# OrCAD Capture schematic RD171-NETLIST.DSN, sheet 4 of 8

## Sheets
4 5: size A3
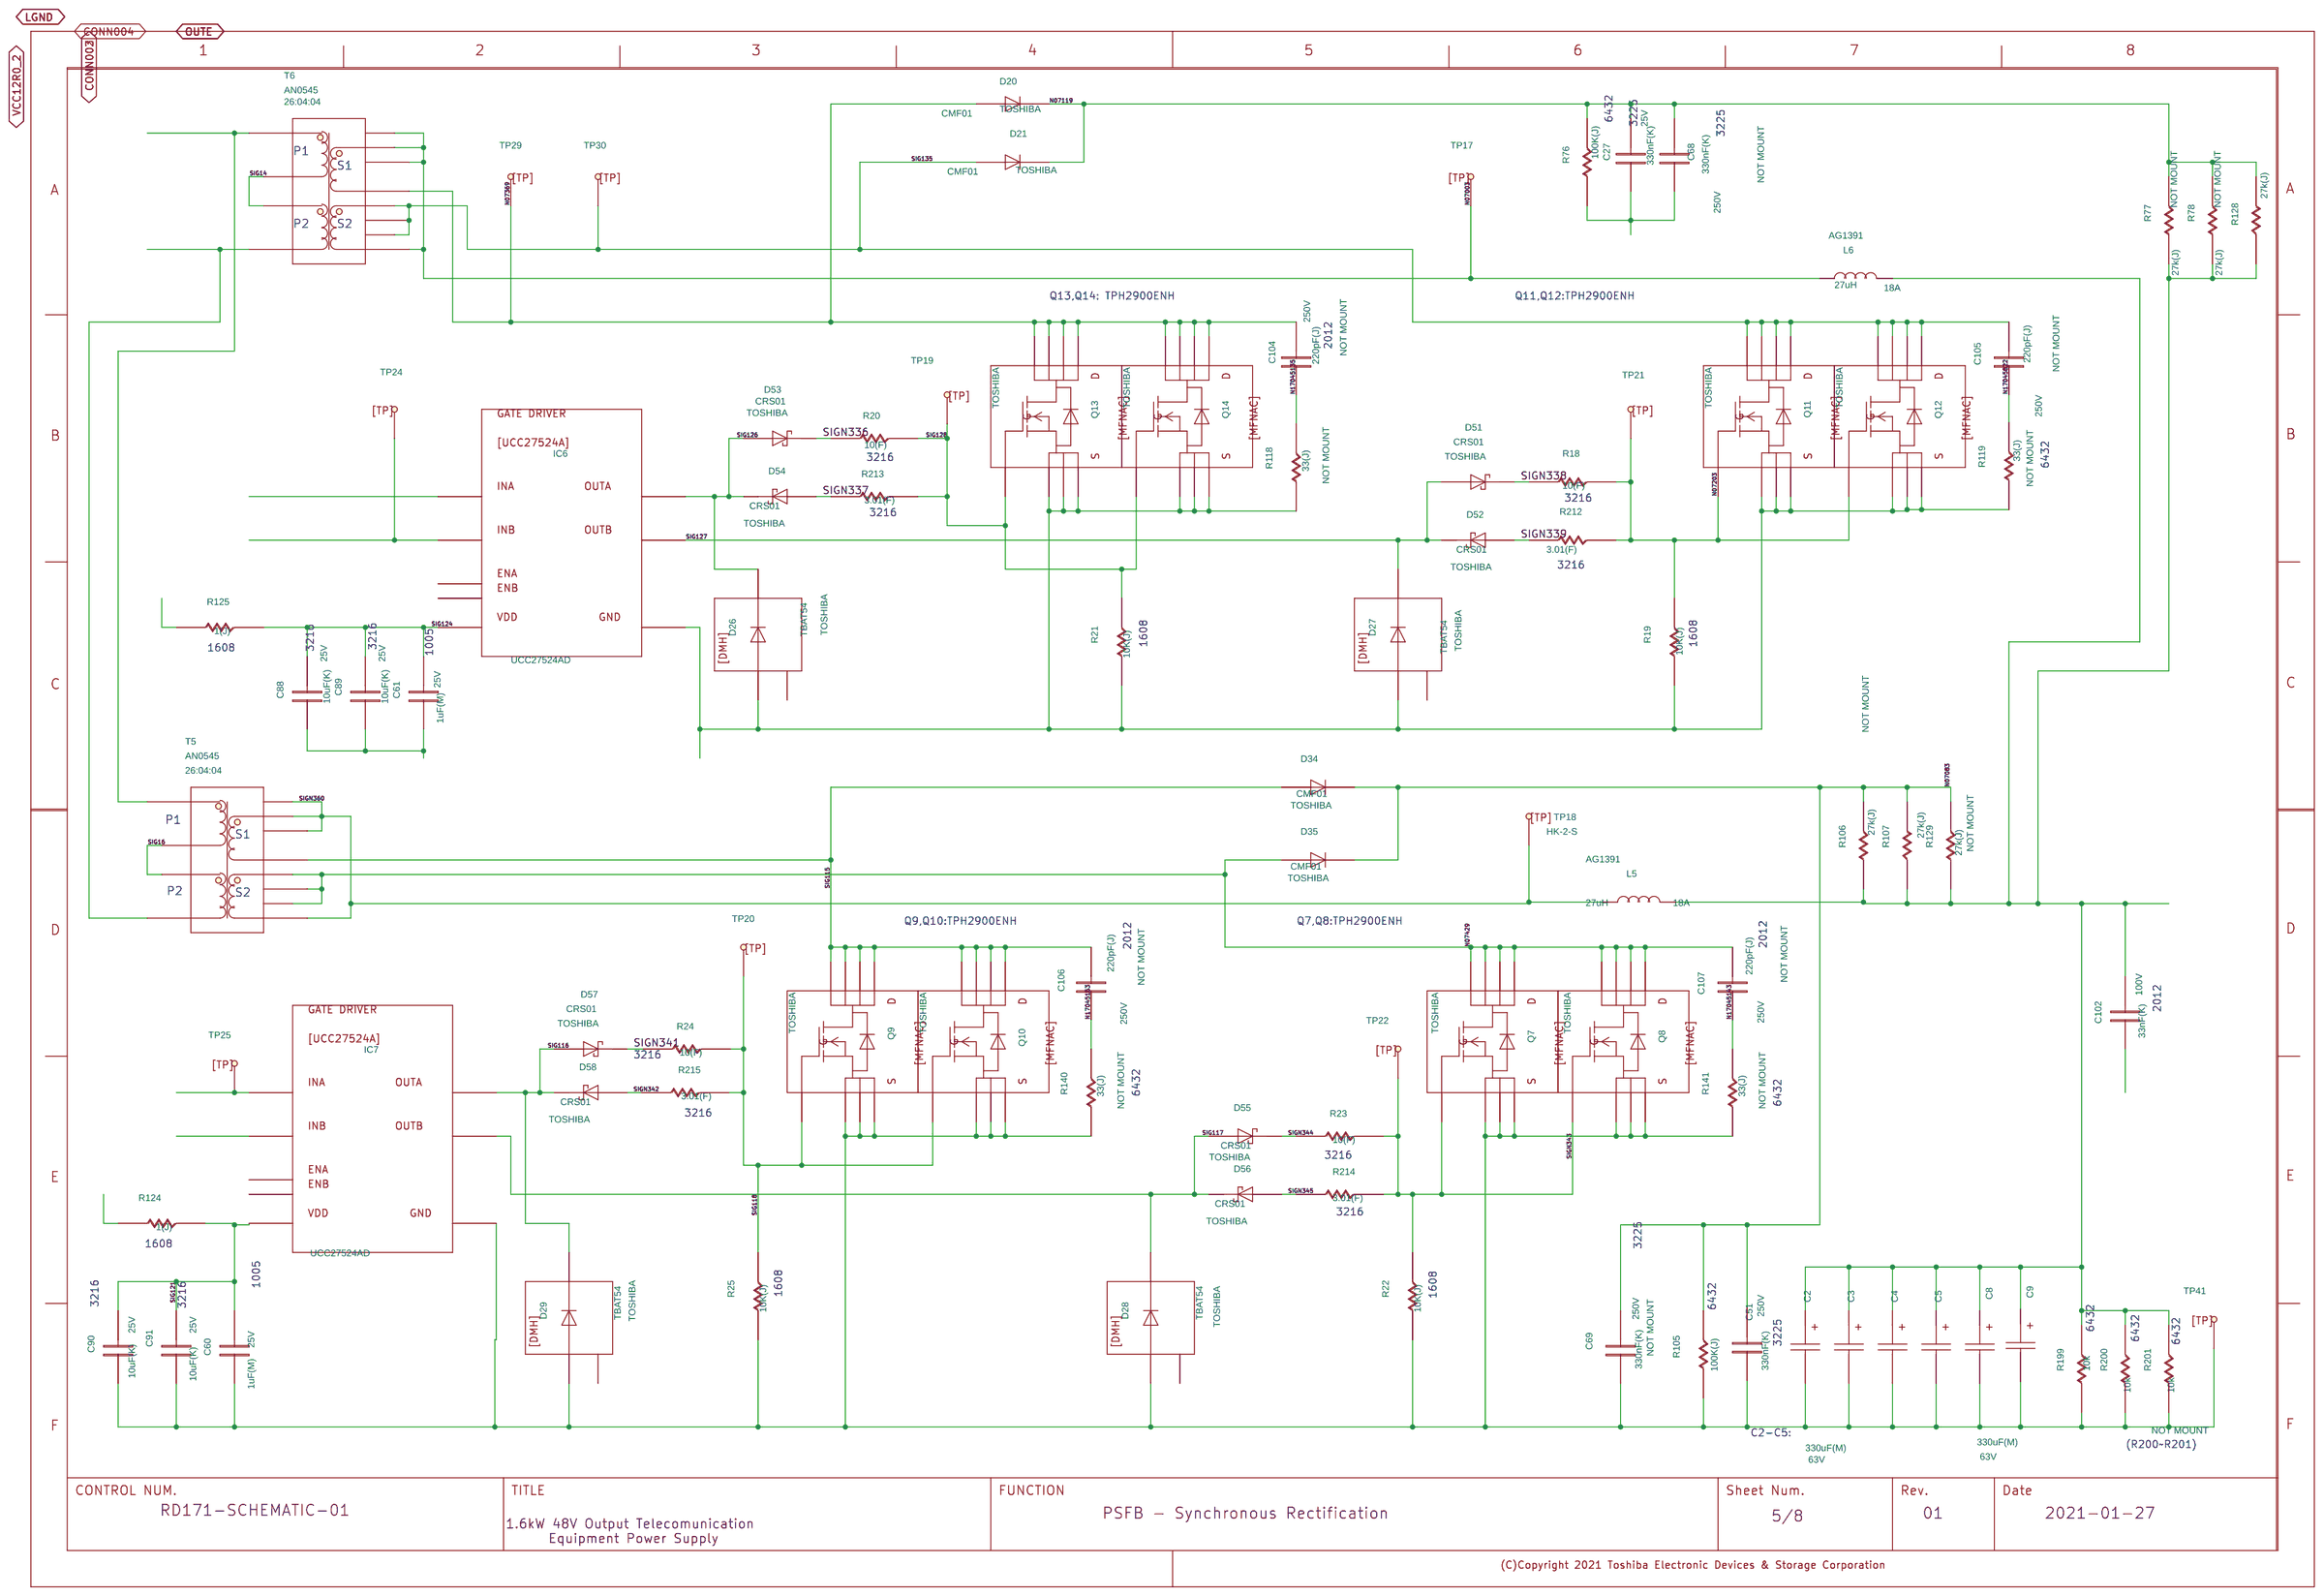
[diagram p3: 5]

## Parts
C2  330uF  [EKZN630ELL331MJ25S]
C3  330uF  [EKZN630ELL331MJ25S]
C4  330uF  [EKZN630ELL331MJ25S]
C5  330uF  [EKZN630ELL331MJ25S]
C8  330uF  [EKZN630ELL331MJ25S]
C9  330uF  [EKZN630ELL331MJ25S]
C27  330nF  [C3225X7T2E334K200AE]
C51  330nF  [C3225X7T2E334K200AE]
C60  1uF
C61  1uF
C68  330nF  [C3225X7T2E334K200AE]
C69  330nF  [C3225X7T2E334K200AE]
C88  10uF
C89  10uF
C90  10uF
C91  10uF
C102  33nF  [C2012C0G2A333J125AE]
C104  220pF  [GRM21A5C221J]
C105  220pF  [GRM21A5C221J]
C106  220pF  [GRM21A5C221J]
C107  220pF  [GRM21A5C221J]
D20  D20  [CMF01]
D21  D21  [CMF01]
D26  D26  [TBAT54]
D27  D27  [TBAT54]
D28  D28  [TBAT54]
D29  D29  [TBAT54]
D34  D34  [CMF01]
D35  D35  [CMF01]
D51  D51  [CRS01]
D52  D52  [CRS01]
D53  D53  [CRS01]
D54  D54  [CRS01]
D55  D55  [CRS01]
D56  D56  [CRS01]
D57  D57  [CRS01]
D58  D58  [CRS01]
IC6  IC6  [UCC27524AD]
IC7  IC7  [UCC27524AD]
L5  27uH  [AG-1391]
L6  27uH  [AG-1391]
Q7  Q7  [TPH2900ENH]
Q8  Q8  [TPH2900ENH]
Q9  Q9  [TPH2900ENH]
Q10  Q10  [TPH2900ENH]
Q11  Q11  [TPH2900ENH]
Q12  Q12  [TPH2900ENH]
Q13  Q13  [TPH2900ENH]
Q14  Q14  [TPH2900ENH]
R18  10
R19  10k
R20  10
R21  10k
R22  10k
R23  10
R24  10
R25  10k
R76  100k  [RK73B3ATTE104J]
R77  R  [MOS3CT631R273J]
R78  27k  [MOS3CT631R273J]
R105  100k  [RK73B3ATTE104J]
R106  27k  [MOS3CT631R273J]
R107  27k  [MOS3CT631R273J]
R118  33  [RK73B3ATTE330J]
R119  33  [RK73B3ATTE330J]
R124  1
R125  1
R128  27k  [MOS3CT631R273J]
R129  27k  [MOS3CT631R273J]
R140  33  [RK73B3ATTE330J]
R141  33  [RK73B3ATTE330J]
R199  10k  [RK73B3ATTE104J]
R200  10k  [RK73B3ATTE104J]
R201  10k  [RK73B3ATTE104J]
R212  3.01
R213  3.01
R214  3.01
R215  3.01
T5  T3_12V67A
T6  T3_12V67A
TP17  TP17  [HK-2-S]
TP18  TP18  [HK-2-S]
TP19  TP19  [HK-2-S]
TP20  TP20  [HK-2-S]
TP21  TP21  [HK-2-S]
TP22  TP22  [HK-2-S]
TP24  TP24  [HK-2-S]
TP25  TP25  [HK-2-S]
TP29  TP29  [HK-2-S]
TP30  TP30  [HK-2-S]
TP41  TP41  [LC-22-S-BLACK]
U?#3  WAKU_DEF100

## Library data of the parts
C2 = CP: CAPACITANCETOLE: M; CDMASTERCADCELG: DC0341; CHIPSIZE: D10xL22; COMP: PRT_3; COMPONENTNAME: CP_CP.Normal_package; FNLEADFREETHET1GT2GMCTH1: 0_2_N; FUNCTION: CP_CP.Normal_package; GCOUNT: 1; INSTANCENAME: INS5781; MAKER: RUBYCON; MAXGCOUNT: 1; NOMINALCAPACITA: 56u; OUMECLASSIFICATION: ƒAƒ‹ƒ~“d‰ðƒRƒ“ƒfƒ“ƒT; OUMEPARTTYPE: C; PARTNAME: EKZN630ELL331MJ25S_CC; PMPRODUCTSTYPEG: SV1; QUADMODEL: CON_56U; RATEDVOLTAGE: 16; SIZECODESMD: DIP; VAL1: 330uF(M); VAL2: 63V
C3 = CP: CAPACITANCETOLE: M; CHIPSIZE: D10xL22; COMP: PRT_3; COMPONENTNAME: CP_CP.Normal_package; FUNCTION: CP_CP.Normal_package; GCOUNT: 1; INSTANCENAME: INS5793; MAKER: RUBYCON; MAXGCOUNT: 1; NOMINALCAPACITA: 56u; PARTNAME: EKZN630ELL331MJ25S_CC; PMPRODUCTSTYPEG: SV1; RATEDVOLTAGE: 16; SIZECODESMD: DIP; VAL1: 330uF(M); VAL2: 63V; VAL3: 25ZLQ1500MEFC10X25
C4 = CP: CAPACITANCETOLE: M; CHIPSIZE: D10xL22; COMP: PRT_3; COMPONENTNAME: CP_CP.Normal_package; FUNCTION: CP_CP.Normal_package; GCOUNT: 1; INSTANCENAME: INS5801; MAKER: RUBYCON; MAXGCOUNT: 1; NOMINALCAPACITA: 56u; PARTNAME: EKZN630ELL331MJ25S_CC; PMPRODUCTSTYPEG: SV1; RATEDVOLTAGE: 16; SIZECODESMD: DIP; VAL1: 330uF(M); VAL2: 63V; VAL3: 25ZLQ1500MEFC10X25
C5 = CP: CAPACITANCETOLE: M; CHIPSIZE: D10xL22; COMP: PRT_3; COMPONENTNAME: CP_CP.Normal_package; FUNCTION: CP_CP.Normal_package; GCOUNT: 1; INSTANCENAME: INS5809; MAKER: RUBYCON; MAXGCOUNT: 1; NOMINALCAPACITA: 56u; PARTNAME: EKZN630ELL331MJ25S_CC; PMPRODUCTSTYPEG: SV1; RATEDVOLTAGE: 16; SIZECODESMD: DIP; VAL1: 330uF(M); VAL2: 63V; VAL3: 25ZLQ1500MEFC10X25
C8 = CP: CAPACITANCETOLE: M; CHIPSIZE: D10xL22; COMP: PRT_3; COMPONENTNAME: CP_CP.Normal_package; FUNCTION: CP_CP.Normal_package; GCOUNT: 1; INSTANCENAME: INS17034209; MAKER: RUBYCON; MAXGCOUNT: 1; NOMINALCAPACITA: 56u; PARTNAME: EKZN630ELL331MJ25S_CC; PMPRODUCTSTYPEG: SV1; RATEDVOLTAGE: 16; SIZECODESMD: DIP; VAL1: 330uF(M); VAL2: 63V; VAL3: EKZN630ELL331M
C9 = CP: CAPACITANCETOLE: M; CHIPSIZE: D10xL22; COMP: PRT_3; COMPONENTNAME: CP_CP.Normal_package; FUNCTION: CP_CP.Normal_package; GCOUNT: 1; INSTANCENAME: INS17035630; MAKER: RUBYCON; MAXGCOUNT: 1; NOMINALCAPACITA: 56u; PARTNAME: EKZN630ELL331MJ25S_CC; PMPRODUCTSTYPEG: SV1; RATEDVOLTAGE: 16; SIZECODESMD: DIP; VAL1: 330uF(M); VAL2: 63V; VAL3: EKZN630ELL331M
C27 = C: ADSMODELNAME: s_C1005JB1C224KT; CAPACITANCETOLE: K; CDMASTERCADCELG: KC0005; CHIPSIZE: 1005; COMP: PRT_52; COMPONENTNAME: C_C.Normal_package; FNLEADFREETHET1GT2GMCTH1: N_N_N; FUNCTION: C_C.Normal_package; GCOUNT: 1; INSTANCENAME: INS6475; MAKER: TDK; MAXGCOUNT: 1; NOMINALCAPACITA: 220n; OUMECLASSIFICATION: ƒZƒ‰ƒ~ƒbƒNƒRƒ“ƒfƒ“ƒT; OUMEMAKER: TDK ‚s‚c‚j; OUMEMAKERKATAMEI: C1005JB1C224KT; PARTNAME: Chip3225_GS_1; QUADMODEL: CON_220N; RATEDVOLTAGE: 16; SIZECODESMD: 1005; TEMPCHARACTERI2: B; VAL1: 330nF(K); VAL2: 25V; VAL3: C1005X5R1E224K050BC
C51 = C: ADSMODELNAME: s_C1005JB1C224KT; CAPACITANCETOLE: K; CDMASTERCADCELG: KC0005; CHIPSIZE: 1005; COMP: PRT_52; COMPONENTNAME: C_C.Normal_package; FNLEADFREETHET1GT2GMCTH1: N_N_N; FUNCTION: C_C.Normal_package; GCOUNT: 1; INSTANCENAME: INS17062697; MAKER: TDK; MAXGCOUNT: 1; NOMINALCAPACITA: 220n; OUMECLASSIFICATION: ƒZƒ‰ƒ~ƒbƒNƒRƒ“ƒfƒ“ƒT; OUMEMAKER: TDK ‚s‚c‚j; PARTNAME: Chip3225_GS_1; QUADMODEL: CON_220N; RATEDVOLTAGE: 16; SIZECODESMD: 3225; TEMPCHARACTERI2: B; VAL1: 330nF(K); VAL2: 250V
C60 = C: ADSMODELNAME: s_GRM155B31E105KA12D; CAPACITANCETOLE: K; CDMASTERCADCELG: KC0005; CHIPSIZE: 1005; COMP: PRT_52; COMPONENTNAME: C_C.Normal_package; FNLEADFREETHET1GT2GMCTH1: 3_0_N; FUNCTION: C_C.Normal_package; GCOUNT: 1; INSTANCENAME: INS6615; MAKER: TDK; MAXGCOUNT: 1; NOMINALCAPACITA: 1u; OUMECLASSIFICATION: ƒZƒ‰ƒ~ƒbƒNƒRƒ“ƒfƒ“ƒT; OUMEMAKER: MRT ºc»ì; OUMEMAKERKATAMEI: GRM155B31E105KA12D; PARTNAME: Chip1005_GS_2; PMPRODUCTSTYPEG: HD1; QUADMODEL: CON_1U; RATEDVOLTAGE: 25; SIZECODESMD: 1005; TEMPCHARACTERI2: B; VAL1: 1uF(M); VAL2: 25V; VAL3: C1005X5R1E105M050BC
C61 = C: ADSMODELNAME: s_GRM155B31E105KA12D; CAPACITANCETOLE: K; CDMASTERCADCELG: KC0005; CHIPSIZE: 1005; COMP: PRT_52; COMPONENTNAME: C_C.Normal_package; FNLEADFREETHET1GT2GMCTH1: 3_0_N; FUNCTION: C_C.Normal_package; GCOUNT: 1; INSTANCENAME: INS6565; MAKER: TDK; MAXGCOUNT: 1; NOMINALCAPACITA: 1u; OUMECLASSIFICATION: ƒZƒ‰ƒ~ƒbƒNƒRƒ“ƒfƒ“ƒT; OUMEMAKER: MRT ºc»ì; OUMEMAKERKATAMEI: GRM155B31E105KA12D; PARTNAME: Chip1005_GS_2; PMPRODUCTSTYPEG: HD1; QUADMODEL: CON_1U; RATEDVOLTAGE: 25; SIZECODESMD: 1005; TEMPCHARACTERI2: B; VAL1: 1uF(M); VAL2: 25V; VAL3: C1005X5R1E105M050BC
C68 = C: ADSMODELNAME: s_C1005JB1C224KT; CAPACITANCETOLE: K; CDMASTERCADCELG: KC0005; CHIPSIZE: 1005; COMP: PRT_52; COMPONENTNAME: C_C.Normal_package; FNLEADFREETHET1GT2GMCTH1: N_N_N; FUNCTION: C_C.Normal_package; GCOUNT: 1; INSTANCENAME: INS17036811; MAKER: TDK; MAXGCOUNT: 1; MOUNT: NOT MOUNT; NOMINALCAPACITA: 220n; NOTMOUNT: NOT MOUNT; OUMECLASSIFICATION: ƒZƒ‰ƒ~ƒbƒNƒRƒ“ƒfƒ“ƒT; OUMEMAKER: TDK ‚s‚c‚j; PARTNAME: Chip3225_GS_1; QUADMODEL: CON_220N; RATEDVOLTAGE: 16; SIZECODESMD: 3225; TEMPCHARACTERI2: B; VAL1: 330nF(K); VAL2: 250V
C69 = C: ADSMODELNAME: s_C1005JB1C224KT; CAPACITANCETOLE: K; CDMASTERCADCELG: KC0005; CHIPSIZE: 1005; COMP: PRT_52; COMPONENTNAME: C_C.Normal_package; FNLEADFREETHET1GT2GMCTH1: N_N_N; FUNCTION: C_C.Normal_package; GCOUNT: 1; INSTANCENAME: INS17039422; MAKER: TDK; MAXGCOUNT: 1; MOUNT: NOT MOUNT; NOMINALCAPACITA: 220n; NOTMOUNT: NOT MOUNT; OUMECLASSIFICATION: ƒZƒ‰ƒ~ƒbƒNƒRƒ“ƒfƒ“ƒT; OUMEMAKER: TDK ‚s‚c‚j; PARTNAME: Chip3225_GS_1; QUADMODEL: CON_220N; RATEDVOLTAGE: 16; SIZECODESMD: 3225; TEMPCHARACTERI2: B; VAL1: 330nF(K); VAL2: 250V
C88 = C: ADSMODELNAME: s_TMK316LD106KL_T; CAPACITANCETOLE: K; CDMASTERCADCELG: KC0014; CHIPSIZE: 3216; COMP: PRT_46; COMPONENTNAME: C_C.Normal_package; FNLEADFREETHET1GT2GMCTH1: N_N_N; FUNCTION: C_C.Normal_package; GCOUNT: 1; INSTANCENAME: INS6555; MAKER: TAIYO YUDEN; MAXGCOUNT: 1; NOMINALCAPACITA: 10u; OUMECLASSIFICATION: ƒZƒ‰ƒ~ƒbƒNƒRƒ“ƒfƒ“ƒT; OUMEMAKER: TYD ‘¾—z—U“d; OUMEMAKERKATAMEI: TMK316LD106KL-T; PARTNAME: Chip3216_GS_1; QUADMODEL: CON_10U; RATEDVOLTAGE: 25; SIZECODESMD: 3216; VAL1: 10uF(K); VAL2: 25V; VAL3: TMK316BJ106KL-T
C89 = C: ADSMODELNAME: s_TMK316LD106KL_T; CAPACITANCETOLE: K; CDMASTERCADCELG: KC0014; CHIPSIZE: 3216; COMP: PRT_46; COMPONENTNAME: C_C.Normal_package; FNLEADFREETHET1GT2GMCTH1: N_N_N; FUNCTION: C_C.Normal_package; GCOUNT: 1; INSTANCENAME: INS6545; MAKER: TAIYO YUDEN; MAXGCOUNT: 1; NOMINALCAPACITA: 10u; OUMECLASSIFICATION: ƒZƒ‰ƒ~ƒbƒNƒRƒ“ƒfƒ“ƒT; OUMEMAKER: TYD ‘¾—z—U“d; OUMEMAKERKATAMEI: TMK316LD106KL-T; PARTNAME: Chip3216_GS_1; QUADMODEL: CON_10U; RATEDVOLTAGE: 25; SIZECODESMD: 3216; VAL1: 10uF(K); VAL2: 25V; VAL3: TMK316BJ106KL-T
C90 = C: ADSMODELNAME: s_TMK316LD106KL_T; CAPACITANCETOLE: K; CDMASTERCADCELG: KC0014; CHIPSIZE: 3216; COMP: PRT_46; COMPONENTNAME: C_C.Normal_package; FNLEADFREETHET1GT2GMCTH1: N_N_N; FUNCTION: C_C.Normal_package; GCOUNT: 1; INSTANCENAME: INS6595; MAKER: TAIYO YUDEN; MAXGCOUNT: 1; NOMINALCAPACITA: 10u; OUMECLASSIFICATION: ƒZƒ‰ƒ~ƒbƒNƒRƒ“ƒfƒ“ƒT; OUMEMAKER: TYD ‘¾—z—U“d; OUMEMAKERKATAMEI: TMK316LD106KL-T; PARTNAME: Chip3216_GS_1; QUADMODEL: CON_10U; RATEDVOLTAGE: 25; SIZECODESMD: 3216; VAL1: 10uF(K); VAL2: 25V; VAL3: TMK316BJ106KL-T
C91 = C: ADSMODELNAME: s_TMK316LD106KL_T; CAPACITANCETOLE: K; CDMASTERCADCELG: KC0014; CHIPSIZE: 3216; COMP: PRT_46; COMPONENTNAME: C_C.Normal_package; FNLEADFREETHET1GT2GMCTH1: N_N_N; FUNCTION: C_C.Normal_package; GCOUNT: 1; INSTANCENAME: INS6605; MAKER: TAIYO YUDEN; MAXGCOUNT: 1; NOMINALCAPACITA: 10u; OUMECLASSIFICATION: ƒZƒ‰ƒ~ƒbƒNƒRƒ“ƒfƒ“ƒT; OUMEMAKER: TYD ‘¾—z—U“d; OUMEMAKERKATAMEI: TMK316LD106KL-T; PARTNAME: Chip3216_GS_1; QUADMODEL: CON_10U; RATEDVOLTAGE: 25; SIZECODESMD: 3216; VAL1: 10uF(K); VAL2: 25V; VAL3: TMK316BJ106KL-T
C102 = C: ADSMODELNAME: s_GRM155R71E104KE14D; CAPACITANCETOLE: K; CDMASTERCADCELG: KC0005; CHIPSIZE: 1005; COMP: PRT_52; COMPONENTNAME: C_C.Normal_package; FNLEADFREETHET1GT2GMCTH1: N_N_N; FUNCTION: C_C.Normal_package; GCOUNT: 1; INSTANCENAME: INS6675; MAKER: TDK; MAXGCOUNT: 1; NOMINALCAPACITA: 100n; OUMECLASSIFICATION: ƒZƒ‰ƒ~ƒbƒNƒRƒ“ƒfƒ“ƒT; OUMEMAKER: MRT ºc»ì; OUMEMAKERKATAMEI: GRM155R71E104KE14D; PARTNAME: Chip2012_GS_1; QUADMODEL: CON_100N; RATEDVOLTAGE: 25; SIZECODESMD: 1005; VAL1: 33nF(K); VAL2: 100V
C104 = C: ADSMODELNAME: s_GRM155R71E104KE14D; CAPACITANCETOLE: K; CDMASTERCADCELG: KC0005; CHIPSIZE: 2012; COMP: PRT_52; COMPONENTNAME: C_C.Normal_package; FNLEADFREETHET1GT2GMCTH1: N_N_N; FUNCTION: C_C.Normal_package; GCOUNT: 1; INSTANCENAME: INS17040886; MAKER: MURATA; MAXGCOUNT: 1; MOUNT: NOT MOUNT; NOMINALCAPACITA: 100n; NOTMOUNT: NOT MOUNT; OUMECLASSIFICATION: ƒZƒ‰ƒ~ƒbƒNƒRƒ“ƒfƒ“ƒT; OUMEMAKER: MRT ºc»ì; OUMEMAKERKATAMEI: GRM21A5C2E221JW01D; PARTNAME: Chip2012_GS_1; QUADMODEL: CON_100N; RATEDVOLTAGE: 250; SIZECODESMD: 2012; VAL1: 220pF(J); VAL2: 250V; VAL3: GRM21A5C2E221J
C105 = C: ADSMODELNAME: s_GRM155R71E104KE14D; CAPACITANCETOLE: K; CDMASTERCADCELG: KC0005; CHIPSIZE: 2012; COMP: PRT_52; COMPONENTNAME: C_C.Normal_package; FNLEADFREETHET1GT2GMCTH1: N_N_N; FUNCTION: C_C.Normal_package; GCOUNT: 1; INSTANCENAME: INS17040900; MAKER: MURATA; MAXGCOUNT: 1; MOUNT: NOT MOUNT; NOMINALCAPACITA: 100n; NOTMOUNT: NOT MOUNT; OUMECLASSIFICATION: ƒZƒ‰ƒ~ƒbƒNƒRƒ“ƒfƒ“ƒT; OUMEMAKER: MRT ºc»ì; OUMEMAKERKATAMEI: GRM21A5C2E221JW01D; PARTNAME: Chip2012_GS_1; QUADMODEL: CON_100N; RATEDVOLTAGE: 250; SIZECODESMD: 2012; VAL1: 220pF(J); VAL2: 250V; VAL3: GRM21A5C2E221J
C106 = C: ADSMODELNAME: s_GRM155R71E104KE14D; CAPACITANCETOLE: K; CDMASTERCADCELG: KC0005; CHIPSIZE: 2012; COMP: PRT_52; COMPONENTNAME: C_C.Normal_package; FNLEADFREETHET1GT2GMCTH1: N_N_N; FUNCTION: C_C.Normal_package; GCOUNT: 1; INSTANCENAME: INS17040913; MAKER: MURATA; MAXGCOUNT: 1; MOUNT: NOT MOUNT; NOMINALCAPACITA: 100n; NOTMOUNT: NOT MOUNT; OUMECLASSIFICATION: ƒZƒ‰ƒ~ƒbƒNƒRƒ“ƒfƒ“ƒT; OUMEMAKER: MRT ºc»ì; OUMEMAKERKATAMEI: GRM21A5C2E221JW01D; PARTNAME: Chip2012_GS_1; QUADMODEL: CON_100N; RATEDVOLTAGE: 250; SIZECODESMD: 2012; VAL1: 220pF(J); VAL2: 250V; VAL3: GRM21A5C2E221J
C107 = C: ADSMODELNAME: s_GRM155R71E104KE14D; CAPACITANCETOLE: K; CDMASTERCADCELG: KC0005; CHIPSIZE: 2012; COMP: PRT_52; COMPONENTNAME: C_C.Normal_package; FNLEADFREETHET1GT2GMCTH1: N_N_N; FUNCTION: C_C.Normal_package; GCOUNT: 1; INSTANCENAME: INS17040926; MAKER: MURATA; MAXGCOUNT: 1; MOUNT: NOT MOUNT; NOMINALCAPACITA: 100n; NOTMOUNT: NOT MOUNT; OUMECLASSIFICATION: ƒZƒ‰ƒ~ƒbƒNƒRƒ“ƒfƒ“ƒT; OUMEMAKER: MRT ºc»ì; OUMEMAKERKATAMEI: GRM21A5C2E221JW01D; PARTNAME: Chip2012_GS_1; QUADMODEL: CON_100N; RATEDVOLTAGE: 250; SIZECODESMD: 2012; VAL1: 220pF(J); VAL2: 250V; VAL3: GRM21A5C2E221J
D20 = D: ADSMODELNAME: s_MURS340T3G@@; CDMASTERCADCELG: KD0125; COMP: PRT_14; COMPONENTNAME: D_D.Normal_package; FNLEADFREETHET1GT2GMCTH1: N_N_N; FORWARDVOLTAGEM: 0; FUNCTION: D_D.Normal_package; GCOUNT: 1; INSTANCENAME: INS5897; MAKER: TOSHIBA; MAXAVERAGEFORWA: 4; MAXGCOUNT: 1; MAXREPETITIVEPE: 400; MAXREVERSEVOLTA: 0; MOUNTINGFORMSMD: SMD; OUMECLASSIFICATION: êÊ®¬fq; OUMEMAKER: ONS IZ~R_N^[; OUMEMAKERKATAMEI: MURS340T3G@@; PARTNAME: CMF01_TS_B; PEAKFORWARDVOLT: 1.28; PMPRODUCTSTYPEG: HEV; REVERSECURRENT: 250u; USERCOMPTEXT3: TOSHIBA; ZENERVOLTAGEMAX: 0; ZENERVOLTAGEMIN: 0
D21 = D: ADSMODELNAME: s_MURS340T3G@@; CDMASTERCADCELG: KD0125; COMP: PRT_14; COMPONENTNAME: D_D.Normal_package; FNLEADFREETHET1GT2GMCTH1: N_N_N; FORWARDVOLTAGEM: 0; FUNCTION: D_D.Normal_package; GCOUNT: 1; INSTANCENAME: INS5909; MAKER: TOSHIBA; MAXAVERAGEFORWA: 4; MAXGCOUNT: 1; MAXREPETITIVEPE: 400; MAXREVERSEVOLTA: 0; MOUNTINGFORMSMD: SMD; OUMECLASSIFICATION: êÊ®¬fq; OUMEMAKER: ONS IZ~R_N^[; OUMEMAKERKATAMEI: MURS340T3G@@; PARTNAME: CMF01_TS_B; PEAKFORWARDVOLT: 1.28; PMPRODUCTSTYPEG: HEV; REVERSECURRENT: 250u; USERCOMPTEXT3: TOSHIBA; ZENERVOLTAGEMAX: 0; ZENERVOLTAGEMIN: 0
D26 = DMH: COMP: PRT_25; COMPONENTNAME: DMH_DMH.Normal_package; FUNCTION: DMH_DMH.Normal_package; INSTANCENAME: INS5825; MAKER: TOSHIBA; PARTNAME: TBAT54_TS_B; USERCOMPTEXT3: TOSHIBA
D27 = DMH: COMP: PRT_25; COMPONENTNAME: DMH_DMH.Normal_package; FUNCTION: DMH_DMH.Normal_package; INSTANCENAME: INS5883; MAKER: TOSHIBA; PARTNAME: TBAT54_TS_B; USERCOMPTEXT3: TOSHIBA
D28 = DMH: COMP: PRT_25; COMPONENTNAME: DMH_DMH.Normal_package; FUNCTION: DMH_DMH.Normal_package; INSTANCENAME: INS5767; MAKER: TOSHIBA; PARTNAME: TBAT54_TS_B; USERCOMPTEXT3: TOSHIBA
D29 = DMH: COMP: PRT_25; COMPONENTNAME: DMH_DMH.Normal_package; FUNCTION: DMH_DMH.Normal_package; INSTANCENAME: INS5753; MAKER: TOSHIBA; PARTNAME: TBAT54_TS_B; USERCOMPTEXT3: TOSHIBA
D34 = D: ADSMODELNAME: s_MURS340T3G@@; CDMASTERCADCELG: KD0125; COMP: PRT_14; COMPONENTNAME: D_D.Normal_package; FNLEADFREETHET1GT2GMCTH1: N_N_N; FORWARDVOLTAGEM: 0; FUNCTION: D_D.Normal_package; GCOUNT: 1; INSTANCENAME: INS5675; MAKER: TOSHIBA; MAXAVERAGEFORWA: 4; MAXGCOUNT: 1; MAXREPETITIVEPE: 400; MAXREVERSEVOLTA: 0; MOUNTINGFORMSMD: SMD; OUMECLASSIFICATION: êÊ®¬fq; OUMEMAKER: ONS IZ~R_N^[; OUMEMAKERKATAMEI: MURS340T3G@@; PARTNAME: CMF01_TS_B; PEAKFORWARDVOLT: 1.28; PMPRODUCTSTYPEG: HEV; REVERSECURRENT: 250u; USERCOMPTEXT3: TOSHIBA; ZENERVOLTAGEMAX: 0; ZENERVOLTAGEMIN: 0
D35 = D: ADSMODELNAME: s_MURS340T3G@@; CDMASTERCADCELG: KD0125; COMP: PRT_14; COMPONENTNAME: D_D.Normal_package; FNLEADFREETHET1GT2GMCTH1: N_N_N; FORWARDVOLTAGEM: 0; FUNCTION: D_D.Normal_package; GCOUNT: 1; INSTANCENAME: INS5663; MAKER: TOSHIBA; MAXAVERAGEFORWA: 4; MAXGCOUNT: 1; MAXREPETITIVEPE: 400; MAXREVERSEVOLTA: 0; MOUNTINGFORMSMD: SMD; OUMECLASSIFICATION: êÊ®¬fq; OUMEMAKER: ONS IZ~R_N^[; OUMEMAKERKATAMEI: MURS340T3G@@; PARTNAME: CMF01_TS_B; PEAKFORWARDVOLT: 1.28; PMPRODUCTSTYPEG: HEV; REVERSECURRENT: 250u; USERCOMPTEXT3: TOSHIBA; ZENERVOLTAGEMAX: 0; ZENERVOLTAGEMIN: 0
D51 = SBD: COMP: PRT_11; COMPONENTNAME: SBD_SBD.Normal_package; FUNCTION: SBD_SBD.Normal_package; INSTANCENAME: INS6339; MAKER: TOSHIBA; PARTNAME: CRS01_TS_B; USERCOMPTEXT3: TOSHIBA
D52 = SBD: COMP: PRT_11; COMPONENTNAME: SBD_SBD.Normal_package; FUNCTION: SBD_SBD.Normal_package; INSTANCENAME: INS6329; MAKER: TOSHIBA; PARTNAME: CRS01_TS_B; USERCOMPTEXT3: TOSHIBA
D53 = SBD: COMP: PRT_11; COMPONENTNAME: SBD_SBD.Normal_package; FUNCTION: SBD_SBD.Normal_package; INSTANCENAME: INS6317; MAKER: TOSHIBA; PARTNAME: CRS01_TS_B; USERCOMPTEXT3: TOSHIBA
D54 = SBD: COMP: PRT_11; COMPONENTNAME: SBD_SBD.Normal_package; FUNCTION: SBD_SBD.Normal_package; INSTANCENAME: INS6307; MAKER: TOSHIBA; PARTNAME: CRS01_TS_B; USERCOMPTEXT3: TOSHIBA
D55 = SBD: COMP: PRT_11; COMPONENTNAME: SBD_SBD.Normal_package; FUNCTION: SBD_SBD.Normal_package; INSTANCENAME: INS6361; MAKER: TOSHIBA; PARTNAME: CRS01_TS_B; USERCOMPTEXT3: TOSHIBA
D56 = SBD: COMP: PRT_11; COMPONENTNAME: SBD_SBD.Normal_package; FUNCTION: SBD_SBD.Normal_package; INSTANCENAME: INS6351; MAKER: TOSHIBA; PARTNAME: CRS01_TS_B; USERCOMPTEXT3: TOSHIBA
D57 = SBD: COMP: PRT_11; COMPONENTNAME: SBD_SBD.Normal_package; FUNCTION: SBD_SBD.Normal_package; INSTANCENAME: INS6383; MAKER: TOSHIBA; PARTNAME: CRS01_TS_B; USERCOMPTEXT3: TOSHIBA
D58 = SBD: COMP: PRT_11; COMPONENTNAME: SBD_SBD.Normal_package; FUNCTION: SBD_SBD.Normal_package; INSTANCENAME: INS6373; MAKER: TOSHIBA; PARTNAME: CRS01_TS_B; USERCOMPTEXT3: TOSHIBA
IC6 = L27524: COMP: PRT_63; COMPONENTNAME: L27524_L27524.Normal_package; FUNCTION: L27524_L27524.Normal_package; INSTANCENAME: INS5965; MAKER: TEXAS; PARTNAME: UCC27524ADR_TI; SAVECOUNT: 1; UPDATEDATE: 2020/07/08; UPDATETIME: 16:40:04
IC7 = L27524: COMP: PRT_63; COMPONENTNAME: L27524_L27524.Normal_package; FUNCTION: L27524_L27524.Normal_package; INSTANCENAME: INS5987; MAKER: TEXAS; PARTNAME: UCC27524ADR_TI; SAVECOUNT: 1; UPDATEDATE: 2020/07/08; UPDATETIME: 16:40:04
L5 = L: ADSMODELNAME: s_LPI_1R2D13; COMP: PRT_40; COMPONENTNAME: L_L.Normal_package; FUNCTION: L_L.Normal_package; GCOUNT: 1; INDUCTANCEMAX: 0; INDUCTANCEMIN: 0; INSTANCENAME: INS6019; MAKER: TOKYO SEIDEN; MAXGCOUNT: 1; MOUNTINGFORMSMD: SMD; NOMINALINDUCTA1: 1.2u; NOMINALINDUCTA2: X; PARTNAME: AG1391_GS; VAL2: 18A; VAL3: AG1391
L6 = L: ADSMODELNAME: s_LPI_1R2D13; COMP: PRT_40; COMPONENTNAME: L_L.Normal_package; FUNCTION: L_L.Normal_package; GCOUNT: 1; INDUCTANCEMAX: 0; INDUCTANCEMIN: 0; INSTANCENAME: INS6033; MAKER: TOKYO SEIDEN; MAXGCOUNT: 1; MOUNTINGFORMSMD: SMD; NOMINALINDUCTA1: 1.2u; NOMINALINDUCTA2: X; PARTNAME: AG1391_GS; VAL2: 18A; VAL3: AG1391
Q7 = MFNAC: COMP: PRT_67; COMPONENTNAME: MFNAC_MFNAC.Normal_package; FUNCTION: MFNAC_MFNAC.Normal_package; INSTANCENAME: INS5731; MAKER: TOSHIBA; PARTNAME: TPH2900ENH_TS; USERCOMPTEXT3: TOSHIBA
Q8 = MFNAC: COMP: PRT_67; COMPONENTNAME: MFNAC_MFNAC.Normal_package; FUNCTION: MFNAC_MFNAC.Normal_package; INSTANCENAME: INS5709; MAKER: TOSHIBA; PARTNAME: TPH2900ENH_TS; USERCOMPTEXT3: TOSHIBA
Q9 = MFNAC: COMP: PRT_67; COMPONENTNAME: MFNAC_MFNAC.Normal_package; FUNCTION: MFNAC_MFNAC.Normal_package; INSTANCENAME: INS6201; MAKER: TOSHIBA; PARTNAME: TPH2900ENH_TS; USERCOMPTEXT3: TOSHIBA
Q10 = MFNAC: COMP: PRT_67; COMPONENTNAME: MFNAC_MFNAC.Normal_package; FUNCTION: MFNAC_MFNAC.Normal_package; INSTANCENAME: INS5641; MAKER: TOSHIBA; PARTNAME: TPH2900ENH_TS; USERCOMPTEXT3: TOSHIBA
Q11 = MFNAC: COMP: PRT_67; COMPONENTNAME: MFNAC_MFNAC.Normal_package; FUNCTION: MFNAC_MFNAC.Normal_package; INSTANCENAME: INS5943; MAKER: TOSHIBA; PARTNAME: TPH2900ENH_TS; USERCOMPTEXT3: TOSHIBA
Q12 = MFNAC: COMP: PRT_67; COMPONENTNAME: MFNAC_MFNAC.Normal_package; FUNCTION: MFNAC_MFNAC.Normal_package; INSTANCENAME: INS5921; MAKER: TOSHIBA; PARTNAME: TPH2900ENH_TS; USERCOMPTEXT3: TOSHIBA
Q13 = MFNAC: COMP: PRT_67; COMPONENTNAME: MFNAC_MFNAC.Normal_package; FUNCTION: MFNAC_MFNAC.Normal_package; INSTANCENAME: INS6179; MAKER: TOSHIBA; PARTNAME: TPH2900ENH_TS; USERCOMPTEXT3: TOSHIBA
Q14 = MFNAC: COMP: PRT_67; COMPONENTNAME: MFNAC_MFNAC.Normal_package; FUNCTION: MFNAC_MFNAC.Normal_package; INSTANCENAME: INS5861; MAKER: TOSHIBA; PARTNAME: TPH2900ENH_TS; USERCOMPTEXT3: TOSHIBA
R18 = R: ADSMODELNAME: s_ERJ8GEYJ3R3V; CDMASTERCADCELG: KC0014; CHIPSIZE: 3216; COMP: PRT_5; COMPONENTNAME: R_R.Normal_package; FNLEADFREETHET1GT2GMCTH1: N_N_N; FUNCTION: R_R.Normal_package; GCOUNT: 1; INSTANCENAME: INS6505; MAKER: VISHAY; MAXGCOUNT: 1; MOUNTINGFORMSMD: SMD; NOMINALRESISTAN: 3.3; OUMECLASSIFICATION: \ÊÀpÅèïRí; OUMEMAKER: NAE pi\jbNGNgjbNfoCX; OUMEMAKERKATAMEI: ERJ8GEYJ3R3V; PARTNAME: Chip3216_GS_1; POWERRATING: 250m; QUADMODEL: RES_3.3; RESISTANCETOLER: J; SIZECODESMD: 3216; VAL1: 10(F); VAL2: 500mW,}1%; VAL3: CRCW12063R01FKEAHP
R19 = R: ADSMODELNAME: s_RK73B1JTTD103J@@; CDMASTERCADCELG: KC0133; CHIPSIZE: 1608; COMP: PRT_8; COMPONENTNAME: R_R.Normal_package; FNLEADFREETHET1GT2GMCTH1: N_N_N; FUNCTION: R_R.Normal_package; GCOUNT: 1; INSTANCENAME: INS6525; MAKER: KOA; MAXGCOUNT: 1; MOUNTINGFORMSMD: SMD; NOMINALRESISTAN: 10K; OUMECLASSIFICATION: \ÊÀpÅèïRí; OUMEMAKER: KOA R[A; OUMEMAKERKATAMEI: RK73B1JTTD103J@@; PARTNAME: Chip1608_GS_1; POWERRATING: 100m; QUADMODEL: RES_10K; RESISTANCETOLER: J; SIZECODESMD: 1608; VAL1: 10K(J); VAL2: 100mW,}5%; VAL3: RK73B1JTTD103J
R20 = R: ADSMODELNAME: s_ERJ8GEYJ3R3V; CDMASTERCADCELG: KC0014; CHIPSIZE: 3216; COMP: PRT_5; COMPONENTNAME: R_R.Normal_package; FNLEADFREETHET1GT2GMCTH1: N_N_N; FUNCTION: R_R.Normal_package; GCOUNT: 1; INSTANCENAME: INS6495; MAKER: VISHAY; MAXGCOUNT: 1; MOUNTINGFORMSMD: SMD; NOMINALRESISTAN: 3.3; OUMECLASSIFICATION: \ÊÀpÅèïRí; OUMEMAKER: NAE pi\jbNGNgjbNfoCX; OUMEMAKERKATAMEI: ERJ8GEYJ3R3V; PARTNAME: Chip3216_GS_1; POWERRATING: 250m; QUADMODEL: RES_3.3; RESISTANCETOLER: J; SIZECODESMD: 3216; VAL1: 10(F); VAL2: 500mW,}1%; VAL3: CRCW12063R01FKEAHP
R21 = R: ADSMODELNAME: s_RK73B1JTTD103J@@; CDMASTERCADCELG: KC0133; CHIPSIZE: 1608; COMP: PRT_8; COMPONENTNAME: R_R.Normal_package; FNLEADFREETHET1GT2GMCTH1: N_N_N; FUNCTION: R_R.Normal_package; GCOUNT: 1; INSTANCENAME: INS6535; MAKER: KOA; MAXGCOUNT: 1; MOUNTINGFORMSMD: SMD; NOMINALRESISTAN: 10K; OUMECLASSIFICATION: \ÊÀpÅèïRí; OUMEMAKER: KOA R[A; OUMEMAKERKATAMEI: RK73B1JTTD103J@@; PARTNAME: Chip1608_GS_1; POWERRATING: 100m; QUADMODEL: RES_10K; RESISTANCETOLER: J; SIZECODESMD: 1608; VAL1: 10K(J); VAL2: 100mW,}5%; VAL3: RK73B1JTTD103J
R22 = R: ADSMODELNAME: s_RK73B1JTTD103J@@; CDMASTERCADCELG: KC0133; CHIPSIZE: 1608; COMP: PRT_8; COMPONENTNAME: R_R.Normal_package; FNLEADFREETHET1GT2GMCTH1: N_N_N; FUNCTION: R_R.Normal_package; GCOUNT: 1; INSTANCENAME: INS6635; MAKER: KOA; MAXGCOUNT: 1; MOUNTINGFORMSMD: SMD; NOMINALRESISTAN: 10K; OUMECLASSIFICATION: \ÊÀpÅèïRí; OUMEMAKER: KOA R[A; OUMEMAKERKATAMEI: RK73B1JTTD103J@@; PARTNAME: Chip1608_GS_1; POWERRATING: 100m; QUADMODEL: RES_10K; RESISTANCETOLER: J; SIZECODESMD: 1608; VAL1: 10K(J); VAL2: 100mW,}5%; VAL3: RK73B1JTTD103J
R23 = R: ADSMODELNAME: s_ERJ8GEYJ3R3V; CDMASTERCADCELG: KC0014; CHIPSIZE: 3216; COMP: PRT_5; COMPONENTNAME: R_R.Normal_package; FNLEADFREETHET1GT2GMCTH1: N_N_N; FUNCTION: R_R.Normal_package; GCOUNT: 1; INSTANCENAME: INS6645; MAKER: VISHAY; MAXGCOUNT: 1; MOUNTINGFORMSMD: SMD; NOMINALRESISTAN: 3.3; OUMECLASSIFICATION: \ÊÀpÅèïRí; OUMEMAKER: NAE pi\jbNGNgjbNfoCX; OUMEMAKERKATAMEI: ERJ8GEYJ3R3V; PARTNAME: Chip3216_GS_1; POWERRATING: 250m; QUADMODEL: RES_3.3; RESISTANCETOLER: J; SIZECODESMD: 3216; VAL1: 10(F); VAL2: 500mW,}1%; VAL3: CRCW12063R01FKEAHP
R24 = R: ADSMODELNAME: s_ERJ8GEYJ3R3V; CDMASTERCADCELG: KC0014; CHIPSIZE: 3216; COMP: PRT_5; COMPONENTNAME: R_R.Normal_package; FNLEADFREETHET1GT2GMCTH1: N_N_N; FUNCTION: R_R.Normal_package; GCOUNT: 1; INSTANCENAME: INS6575; MAKER: VISHAY; MAXGCOUNT: 1; MOUNTINGFORMSMD: SMD; NOMINALRESISTAN: 3.3; OUMECLASSIFICATION: \ÊÀpÅèïRí; OUMEMAKER: NAE pi\jbNGNgjbNfoCX; OUMEMAKERKATAMEI: ERJ8GEYJ3R3V; PARTNAME: Chip3216_GS_1; POWERRATING: 250m; QUADMODEL: RES_3.3; RESISTANCETOLER: J; SIZECODESMD: 3216; VAL1: 10(F); VAL2: 500mW,}1%; VAL3: CRCW12063R01FKEAHP
R25 = R: ADSMODELNAME: s_RK73B1JTTD103J@@; CDMASTERCADCELG: KC0133; CHIPSIZE: 1608; COMP: PRT_8; COMPONENTNAME: R_R.Normal_package; FNLEADFREETHET1GT2GMCTH1: N_N_N; FUNCTION: R_R.Normal_package; GCOUNT: 1; INSTANCENAME: INS6625; MAKER: KOA; MAXGCOUNT: 1; MOUNTINGFORMSMD: SMD; NOMINALRESISTAN: 10K; OUMECLASSIFICATION: \ÊÀpÅèïRí; OUMEMAKER: KOA R[A; OUMEMAKERKATAMEI: RK73B1JTTD103J@@; PARTNAME: Chip1608_GS_1; POWERRATING: 100m; QUADMODEL: RES_10K; RESISTANCETOLER: J; SIZECODESMD: 1608; VAL1: 10K(J); VAL2: 100mW,}5%; VAL3: RK73B1JTTD103J
R76 = R: ADSCOMPONENTNAME: R_3216; ADSMODELNAME: s_RK73H2BTTD1003F@@; CHIPSIZE: 3216; COMP: PRT_5; COMPONENTNAME: R_R.Normal_package; FUNCTION: R_R.Normal_package; GCOUNT: 1; INSTANCENAME: INS6097; MAKER: PANASONIC; MAXGCOUNT: 1; MOUNTINGFORMSMD: SMD; PARTNAME: Chip6432_GS; PMPRODUCTSTYPEG: DA; SIZECODESMD: 3216; VAL1: 100K(J); VAL2: 250mW,}5%
R77 = R: CDMASTERCADCELG: AXK0015; COMP: PRT_54; COMPONENTNAME: R_R.Normal_package; FNLEADFREETHET1GT2GMCTH1: N_N_N; FUNCTION: R_R.Normal_package; GCOUNT: 1; INSTANCENAME: INS6107; MAKER: VISHAY; MAXGCOUNT: 1; MOUNTINGFORMSMD: DIP; NOMINALRESISTAN: 100; NOTMOUNT: NOT MOUNT; OUMECLASSIFICATION: _»à®çÅèïRí; OUMEMAKER: KOA R[A; OUMEMAKERKATAMEI: MOS3CT521A101J@@; PARTNAME: MOS3C_KO; PMPRODUCTSTYPEG: HEV; POWERRATING: 3; QUADMODEL: RES_100; RESISTANCETOLER: J; VAL1: 27k(J); VAL2: NOT MOUNT; VAL3: PR03000201001JAC00
R78 = R: CDMASTERCADCELG: AXK0015; COMP: PRT_54; COMPONENTNAME: R_R.Normal_package; FNLEADFREETHET1GT2GMCTH1: N_N_N; FUNCTION: R_R.Normal_package; GCOUNT: 1; INSTANCENAME: INS6133; MAKER: VISHAY; MAXGCOUNT: 1; MOUNTINGFORMSMD: DIP; NOMINALRESISTAN: 100; NOTMOUNT: NOT MOUNT; OUMECLASSIFICATION: _»à®çÅèïRí; OUMEMAKER: KOA R[A; OUMEMAKERKATAMEI: MOS3CT521A101J@@; PARTNAME: MOS3C_KO; PMPRODUCTSTYPEG: HEV; POWERRATING: 3; QUADMODEL: RES_100; RESISTANCETOLER: J; VAL1: 27k(J); VAL2: NOT MOUNT; VAL3: PR03000201001JAC00
R105 = R: ADSCOMPONENTNAME: R_3216; ADSMODELNAME: s_RK73H2BTTD1003F@@; CHIPSIZE: 3216; COMP: PRT_5; COMPONENTNAME: R_R.Normal_package; FUNCTION: R_R.Normal_package; GCOUNT: 1; INSTANCENAME: INS6047; MAKER: PANASONIC; MAXGCOUNT: 1; MOUNTINGFORMSMD: SMD; PARTNAME: Chip6432_GS; PMPRODUCTSTYPEG: DA; SIZECODESMD: 3216; VAL1: 100K(J); VAL2: 250mW,}5%
R106 = R: CDMASTERCADCELG: AXK0015; COMP: PRT_54; COMPONENTNAME: R_R.Normal_package; FNLEADFREETHET1GT2GMCTH1: N_N_N; FUNCTION: R_R.Normal_package; GCOUNT: 1; INSTANCENAME: INS6057; MAKER: VISHAY; MAXGCOUNT: 1; MOUNTINGFORMSMD: DIP; NOMINALRESISTAN: 100; NOTMOUNT: NOT MOUNT; OUMECLASSIFICATION: _»à®çÅèïRí; OUMEMAKER: KOA R[A; OUMEMAKERKATAMEI: MOS3CT521A101J@@; PARTNAME: MOS3C_KO; PMPRODUCTSTYPEG: HEV; POWERRATING: 3; QUADMODEL: RES_100; RESISTANCETOLER: J; VAL1: 27k(J); VAL2: NOT MOUNT; VAL3: PR03000201001JAC00
R107 = R: CDMASTERCADCELG: AXK0015; COMP: PRT_54; COMPONENTNAME: R_R.Normal_package; FNLEADFREETHET1GT2GMCTH1: N_N_N; FUNCTION: R_R.Normal_package; GCOUNT: 1; INSTANCENAME: INS6069; MAKER: VISHAY; MAXGCOUNT: 1; MOUNTINGFORMSMD: DIP; NOMINALRESISTAN: 100; OUMECLASSIFICATION: _»à®çÅèïRí; OUMEMAKER: KOA R[A; OUMEMAKERKATAMEI: MOS3CT521A101J@@; PARTNAME: MOS3C_KO; PMPRODUCTSTYPEG: HEV; POWERRATING: 3; QUADMODEL: RES_100; RESISTANCETOLER: J; VAL1: 27k(J); VAL2: 3W,}5%; VAL3: PR03000201001JAC00
R118 = R: ADSCOMPONENTNAME: R_3216; ADSMODELNAME: s_RK73H2BTTD1003F@@; CHIPSIZE: 3216; COMP: PRT_5; COMPONENTNAME: R_R.Normal_package; FUNCTION: R_R.Normal_package; GCOUNT: 1; INSTANCENAME: INS17040861; MAKER: KOA; MAXGCOUNT: 1; MOUNT: NOT MOUNT; MOUNTINGFORMSMD: SMD; NOTMOUNT: NOT MOUNT; PARTNAME: Chip6432_GS; PMPRODUCTSTYPEG: DA; SIZECODESMD: 6432; VAL1: 33(J); VAL2: 1W,E}%
R119 = R: ADSCOMPONENTNAME: R_3216; ADSMODELNAME: s_RK73H2BTTD1003F@@; CHIPSIZE: 3216; COMP: PRT_5; COMPONENTNAME: R_R.Normal_package; FUNCTION: R_R.Normal_package; GCOUNT: 1; INSTANCENAME: INS17040874; MAKER: KOA; MAXGCOUNT: 1; MOUNT: NOT MOUNT; MOUNTINGFORMSMD: SMD; NOTMOUNT: NOT MOUNT; PARTNAME: Chip6432_GS; PMPRODUCTSTYPEG: DA; SIZECODESMD: 6432; VAL1: 33(J); VAL2: 1W,E}%
R124 = R: ADSMODELNAME: s_ERJ3GEYJ1R0V; CDMASTERCADCELG: KC0008; CHIPSIZE: 1608; COMP: PRT_8; COMPONENTNAME: R_R.Normal_package; FNLEADFREETHET1GT2GMCTH1: 2_1_N; FUNCTION: R_R.Normal_package; INSTANCENAME: INS6009; MAKER: PANASONIC; MOUNTINGFORMSMD: SMD; OUMECLASSIFICATION: \ÊÀpÅèïRí; OUMEMAKER: NAE pi\jbNGNgjbNfoCX; OUMEMAKERKATAMEI: ERJ3GEYJ1R0V; PARTNAME: Chip1608_GS_1; PMPRODUCTSTYPEG: PC1; POWERRATING: 63m; QUADMODEL: RES_1; RESISTANCETOLER: J; SIZECODESMD: 1608; VAL1: 1(J); VAL2: 100mW,}5%; VAL3: ERJ-3GEYJ1R0V
R125 = R: ADSMODELNAME: s_ERJ3GEYJ1R0V; CDMASTERCADCELG: KC0008; CHIPSIZE: 1608; COMP: PRT_8; COMPONENTNAME: R_R.Normal_package; FNLEADFREETHET1GT2GMCTH1: 2_1_N; FUNCTION: R_R.Normal_package; INSTANCENAME: INS6147; MAKER: PANASONIC; MOUNTINGFORMSMD: SMD; OUMECLASSIFICATION: \ÊÀpÅèïRí; OUMEMAKER: NAE pi\jbNGNgjbNfoCX; OUMEMAKERKATAMEI: ERJ3GEYJ1R0V; PARTNAME: Chip1608_GS_1; PMPRODUCTSTYPEG: PC1; POWERRATING: 63m; QUADMODEL: RES_1; RESISTANCETOLER: J; SIZECODESMD: 1608; VAL1: 1(J); VAL2: 100mW,}5%; VAL3: ERJ-3GEYJ1R0V
R128 = R: CDMASTERCADCELG: AXK0015; COMP: PRT_54; COMPONENTNAME: R_R.Normal_package; FNLEADFREETHET1GT2GMCTH1: N_N_N; FUNCTION: R_R.Normal_package; GCOUNT: 1; INSTANCENAME: INS6119; MAKER: VISHAY; MAXGCOUNT: 1; MOUNTINGFORMSMD: DIP; NOMINALRESISTAN: 100; OUMECLASSIFICATION: _»à®çÅèïRí; OUMEMAKER: KOA R[A; OUMEMAKERKATAMEI: MOS3CT521A101J@@; PARTNAME: MOS3C_KO; PMPRODUCTSTYPEG: HEV; POWERRATING: 3; QUADMODEL: RES_100; RESISTANCETOLER: J; VAL1: 27k(J); VAL2: 3W,}5%; VAL3: PR03000201001JAC00
R129 = R: CDMASTERCADCELG: AXK0015; COMP: PRT_54; COMPONENTNAME: R_R.Normal_package; FNLEADFREETHET1GT2GMCTH1: N_N_N; FUNCTION: R_R.Normal_package; GCOUNT: 1; INSTANCENAME: INS6083; MAKER: VISHAY; MAXGCOUNT: 1; MOUNTINGFORMSMD: DIP; NOMINALRESISTAN: 100; NOTMOUNT: NOT MOUNT; OUMECLASSIFICATION: _»à®çÅèïRí; OUMEMAKER: KOA R[A; OUMEMAKERKATAMEI: MOS3CT521A101J@@; PARTNAME: MOS3C_KO; PMPRODUCTSTYPEG: HEV; POWERRATING: 3; QUADMODEL: RES_100; RESISTANCETOLER: J; VAL1: 27k(J); VAL2: NOT MOUNT; VAL3: PR03000201001JAC00
R140 = R: ADSCOMPONENTNAME: R_3216; ADSMODELNAME: s_RK73H2BTTD1003F@@; CHIPSIZE: 3216; COMP: PRT_5; COMPONENTNAME: R_R.Normal_package; FUNCTION: R_R.Normal_package; GCOUNT: 1; INSTANCENAME: INS17041940; MAKER: KOA; MAXGCOUNT: 1; MOUNT: NOT MOUNT; MOUNTINGFORMSMD: SMD; NOTMOUNT: NOT MOUNT; PARTNAME: Chip6432_GS; PMPRODUCTSTYPEG: DA; SIZECODESMD: 6432; VAL1: 33(J); VAL2: 1W,E}%
R141 = R: ADSCOMPONENTNAME: R_3216; ADSMODELNAME: s_RK73H2BTTD1003F@@; CHIPSIZE: 3216; COMP: PRT_5; COMPONENTNAME: R_R.Normal_package; FUNCTION: R_R.Normal_package; GCOUNT: 1; INSTANCENAME: INS17040848; MAKER: KOA; MAXGCOUNT: 1; MOUNT: NOT MOUNT; MOUNTINGFORMSMD: SMD; NOTMOUNT: NOT MOUNT; PARTNAME: Chip6432_GS; PMPRODUCTSTYPEG: DA; SIZECODESMD: 6432; VAL1: 33(J); VAL2: 1W,E}%
R199 = R: CHIPSIZE: 6432; COMP: PRT_43; COMPONENTNAME: R_R.Normal_package; FUNCTION: R_R.Normal_package; GCOUNT: 1; INSTANCENAME: INS6245; MAKER: VISHAY; MAXGCOUNT: 1; MOUNTINGFORMSMD: DIP; PARTNAME: Chip6432_GS; PMPRODUCTSTYPEG: HEV; VAL2: 1W,}5%; VAL3: CRCW2512680RFKEG
R200 = R: CHIPSIZE: 6432; COMP: PRT_43; COMPONENTNAME: R_R.Normal_package; FUNCTION: R_R.Normal_package; GCOUNT: 1; INSTANCENAME: INS6257; MAKER: VISHAY; MAXGCOUNT: 1; MOUNTINGFORMSMD: DIP; NOTMOUNT: NOT MOUNT; PARTNAME: Chip6432_GS; PMPRODUCTSTYPEG: HEV; VAL2: 1W,}5%; VAL3: CRCW2512680RFKEG
R201 = R: CHIPSIZE: 6432; COMP: PRT_43; COMPONENTNAME: R_R.Normal_package; FUNCTION: R_R.Normal_package; GCOUNT: 1; INSTANCENAME: INS6271; MAKER: VISHAY; MAXGCOUNT: 1; MOUNTINGFORMSMD: DIP; NOTMOUNT: NOT MOUNT; PARTNAME: Chip6432_GS; PMPRODUCTSTYPEG: HEV; VAL2: 1W,}5%; VAL3: CRCW2512680RFKEG
R212 = R: ADSMODELNAME: s_ERJ8GEYJ3R3V; CDMASTERCADCELG: KC0014; CHIPSIZE: 3216; COMP: PRT_5; COMPONENTNAME: R_R.Normal_package; FNLEADFREETHET1GT2GMCTH1: N_N_N; FUNCTION: R_R.Normal_package; GCOUNT: 1; INSTANCENAME: INS6515; MAKER: VISHAY; MAXGCOUNT: 1; MOUNTINGFORMSMD: SMD; NOMINALRESISTAN: 3.3; OUMECLASSIFICATION: \ÊÀpÅèïRí; OUMEMAKER: NAE pi\jbNGNgjbNfoCX; OUMEMAKERKATAMEI: ERJ8GEYJ3R3V; PARTNAME: Chip3216_GS_1; POWERRATING: 250m; QUADMODEL: RES_3.3; RESISTANCETOLER: J; SIZECODESMD: 3216; VAL1: 3.01(F); VAL2: 500mW,}1%; VAL3: CRCW12063R01FKEAHP
R213 = R: ADSMODELNAME: s_ERJ8GEYJ3R3V; CDMASTERCADCELG: KC0014; CHIPSIZE: 3216; COMP: PRT_5; COMPONENTNAME: R_R.Normal_package; FNLEADFREETHET1GT2GMCTH1: N_N_N; FUNCTION: R_R.Normal_package; GCOUNT: 1; INSTANCENAME: INS6485; MAKER: VISHAY; MAXGCOUNT: 1; MOUNTINGFORMSMD: SMD; NOMINALRESISTAN: 3.3; OUMECLASSIFICATION: \ÊÀpÅèïRí; OUMEMAKER: NAE pi\jbNGNgjbNfoCX; OUMEMAKERKATAMEI: ERJ8GEYJ3R3V; PARTNAME: Chip3216_GS_1; POWERRATING: 250m; QUADMODEL: RES_3.3; RESISTANCETOLER: J; SIZECODESMD: 3216; VAL1: 3.01(F); VAL2: 500mW,}1%; VAL3: CRCW12063R01FKEAHP
R214 = R: ADSMODELNAME: s_ERJ8GEYJ3R3V; CDMASTERCADCELG: KC0014; CHIPSIZE: 3216; COMP: PRT_5; COMPONENTNAME: R_R.Normal_package; FNLEADFREETHET1GT2GMCTH1: N_N_N; FUNCTION: R_R.Normal_package; GCOUNT: 1; INSTANCENAME: INS6655; MAKER: VISHAY; MAXGCOUNT: 1; MOUNTINGFORMSMD: SMD; NOMINALRESISTAN: 3.3; OUMECLASSIFICATION: \ÊÀpÅèïRí; OUMEMAKER: NAE pi\jbNGNgjbNfoCX; OUMEMAKERKATAMEI: ERJ8GEYJ3R3V; PARTNAME: Chip3216_GS_1; POWERRATING: 250m; QUADMODEL: RES_3.3; RESISTANCETOLER: J; SIZECODESMD: 3216; VAL1: 3.01(F); VAL2: 500mW,}1%; VAL3: CRCW12063R01FKEAHP
R215 = R: ADSMODELNAME: s_ERJ8GEYJ3R3V; CDMASTERCADCELG: KC0014; CHIPSIZE: 3216; COMP: PRT_5; COMPONENTNAME: R_R.Normal_package; FNLEADFREETHET1GT2GMCTH1: N_N_N; FUNCTION: R_R.Normal_package; GCOUNT: 1; INSTANCENAME: INS6585; MAKER: VISHAY; MAXGCOUNT: 1; MOUNTINGFORMSMD: SMD; NOMINALRESISTAN: 3.3; OUMECLASSIFICATION: \ÊÀpÅèïRí; OUMEMAKER: NAE pi\jbNGNgjbNfoCX; OUMEMAKERKATAMEI: ERJ8GEYJ3R3V; PARTNAME: Chip3216_GS_1; POWERRATING: 250m; QUADMODEL: RES_3.3; RESISTANCETOLER: J; SIZECODESMD: 3216; VAL1: 3.01(F); VAL2: 500mW,}1%; VAL3: CRCW12063R01FKEAHP
T5 T6 = T3_8: PARTNAME: AN0545_GS; SAVEAREA0: -9959,-21887,29530,7064; SAVECOUNT: 3; UPDATEDATE: 2020/07/09; UPDATETIME: 15:16:45; VAL1: 26:04:04; VAL3: AN0545
TP17 = TP: COMP: PRT_44; COMPONENTNAME: TP_TP.Normal_package; FUNCTION: TP_TP.Normal_package; INSTANCENAME: INS6701; MAKER: MAC8; PARTNAME: HK-2_M8
TP18 = TP: COMP: PRT_44; COMPONENTNAME: TP_TP.Normal_package; FUNCTION: TP_TP.Normal_package; INSTANCENAME: INS6725; MAKER: MAC8; PARTNAME: HK-2_M8
TP19 = TP: COMP: PRT_44; COMPONENTNAME: TP_TP.Normal_package; FUNCTION: TP_TP.Normal_package; ID: Q13-G; INSTANCENAME: INS6749; MAKER: MAC8; PARTNAME: HK-2_M8
TP20 = TP: COMP: PRT_44; COMPONENTNAME: TP_TP.Normal_package; FUNCTION: TP_TP.Normal_package; ID: Q9-G; INSTANCENAME: INS6717; MAKER: MAC8; PARTNAME: HK-2_M8
TP21 = TP: COMP: PRT_44; COMPONENTNAME: TP_TP.Normal_package; FUNCTION: TP_TP.Normal_package; ID: Q11-G; INSTANCENAME: INS6685; MAKER: MAC8; PARTNAME: HK-2_M8
TP22 = TP: COMP: PRT_44; COMPONENTNAME: TP_TP.Normal_package; FUNCTION: TP_TP.Normal_package; ID: Q7-G; INSTANCENAME: INS6709; MAKER: MAC8; PARTNAME: HK-2_M8
TP24 = TP: COMP: PRT_44; COMPONENTNAME: TP_TP.Normal_package; FUNCTION: TP_TP.Normal_package; ID: OUTF; INSTANCENAME: INS6765; MAKER: MAC8; PARTNAME: HK-2_M8
TP25 = TP: COMP: PRT_44; COMPONENTNAME: TP_TP.Normal_package; FUNCTION: TP_TP.Normal_package; ID: OUTE; INSTANCENAME: INS6773; MAKER: MAC8; PARTNAME: HK-2_M8
TP29 = TP: COMP: PRT_44; COMPONENTNAME: TP_TP.Normal_package; FUNCTION: TP_TP.Normal_package; INSTANCENAME: INS6733; MAKER: MAC8; PARTNAME: HK-2_M8
TP30 = TP: COMP: PRT_44; COMPONENTNAME: TP_TP.Normal_package; FUNCTION: TP_TP.Normal_package; INSTANCENAME: INS6741; MAKER: MAC8; PARTNAME: HK-2_M8
TP41 = TP: COMP: PRT_34; COMPONENTNAME: TP_TP.Normal_package; FUNCTION: TP_TP.Normal_package; ID: LGND; INSTANCENAME: INS6797; MAKER: MAC8; PARTNAME: LC-22_GS
U?#3 = WAKU_DEF100: DATE: 2021-01-27; DRAWINGNUMBER: RD171-SCHEMATIC-01; FUNCTION: PSFB - Synchronous Rectification; REVISION: 01; SAVEAREA0: 168739,-66042,466246,90057; SAVECOUNT: 5; SHEETNUMBER: 5/8; TITLE: 1.6kW 48V Output Telecomunication / Equipment Power Supply; UPDATEDATE: 2021/01/27; UPDATETIME: 15:56:17

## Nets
VCC12R0_2: R124.1 R125.1 ; also on sheet 1 3
CONN002: T5.1 T6.1 ; also on sheet 5
CONN003: T5.6 T6.6 ; also on sheet 5
CONN004: C2.2 C3.2 C4.2 C5.2 C8.2 C9.2 C102.2 L5.2 L6.2 R77.1 R78.1 R106.1 R107.2 R128.2 R129.1 R199.2 R200.2 R201.2 ; also on sheet 1 3
LGND: C2.1 C3.1 C4.1 C5.1 C8.1 C9.1 C27.1 C51.1 C60.1 C61.1 C68.1 C69.1 C88.1 C89.1 C90.1 C91.1 C102.1 D26.A D27.A D28.A D29.A IC6.3 IC7.3 Q7.1 Q7.2 Q7.3 Q8.1 Q8.2 Q8.3 Q9.1 Q9.2 Q9.3 Q10.1 Q10.2 Q10.3 Q11.1 Q11.2 Q11.3 Q12.1 Q12.2 Q12.3 Q13.1 Q13.2 Q13.3 Q14.1 Q14.2 Q14.3 R19.1 R21.1 R22.1 R25.1 R76.1 R105.1 R118.1 R119.1 R140.1 R141.1 R199.1 R200.1 R201.1 TP41.1 ; also on sheet 1 2 3 5 8
OUTE: IC6.2 IC7.2 TP25.1 ; also on sheet 3
OUTF: IC6.4 IC7.4 TP24.1 ; also on sheet 3
SIG14: T6.3 T6.4
SIG16: T5.3 T5.4
SIG115: C106.2 D34.A Q9.5 Q9.6 Q9.7 Q9.8 Q10.5 Q10.6 Q10.7 Q10.8 T5.14
SIG116: D29.C D57.A D58.C IC7.7
SIG117: D28.C D55.A D56.C IC7.5
SIG118: Q9.4 Q10.4 R24.2 R25.2 R215.2 TP20.1
SIG121: C60.2 C90.2 C91.2 IC7.6 R124.2
SIG124: C61.2 C88.2 C89.2 IC6.6 R125.2
SIG126: D26.C D53.A D54.C IC6.7
SIG127: D27.C D51.A D52.C IC6.5
SIG128: Q13.4 Q14.4 R20.2 R21.2 R213.2 TP19.1
SIG135: C105.2 D21.A Q11.5 Q11.6 Q11.7 Q11.8 Q12.5 Q12.6 Q12.7 Q12.8 T6.10 T6.11 T6.12 TP30.1
SIGN336: D53.C R20.1
SIGN337: D54.A R213.1
SIGN338: D51.C R18.1
SIGN339: D52.A R212.1
SIGN341: D57.C R24.1
SIGN342: D58.A R215.1
SIGN343: Q7.4 Q8.4 R22.2 R23.2 R214.2 TP22.1
SIGN344: D55.C R23.1
SIGN345: D56.A R214.1
SIGN360: L5.1 T5.7 T5.8 T5.9 T5.13 TP18.1
N07003: L6.1 T6.7 T6.8 T6.9 T6.13 TP17.1
N07083: C51.2 C69.2 D34.C D35.C R105.2 R106.2 R107.1 R129.2
N07119: C27.2 C68.2 D20.C D21.C R76.2 R77.2 R78.2 R128.1
N07203: Q11.4 Q12.4 R18.2 R19.2 R212.2 TP21.1
N07369: C104.2 D20.A Q13.5 Q13.6 Q13.7 Q13.8 Q14.5 Q14.6 Q14.7 Q14.8 T6.14 TP29.1
N07429: C107.2 D35.A Q7.5 Q7.6 Q7.7 Q7.8 Q8.5 Q8.6 Q8.7 Q8.8 T5.10 T5.11 T5.12
N17045135: C104.1 R118.2
N17045143: C107.1 R141.2
N17045153: C106.1 R140.2
N17045822: C105.1 R119.2

Not connected (* = marked no-connect by the designer): D26 NC; D27 NC; D28 NC; D29 NC; IC6 1 8; IC7 1 8

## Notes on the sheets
sheet 4
- 6432
- 3225
- P1
- 3225
- S1
- P2
- S2
- Q13,Q14: TPH2900ENH
- Q11,Q12:TPH2900ENH
- 2012
- 3216
- 6432
- 3216
- 3216
- 3216
- 1608
- 3216
- 3216
- 1005
- 1608
- 1608
- P1
- S1
- P2
- S2
- Q9,Q10:TPH2900ENH
- Q7,Q8:TPH2900ENH
- 2012
- 2012
- 2012
- 3216
- 3216
- 6432
- 6432
- 3216
- 3216
- 1608
- 3225
- 1005
- 1608
- 3216
- 3216
- 1608
- 6432
- 6432
- 3225
- 6432
- 6432
- C2-C5:
- (R200~R201)
